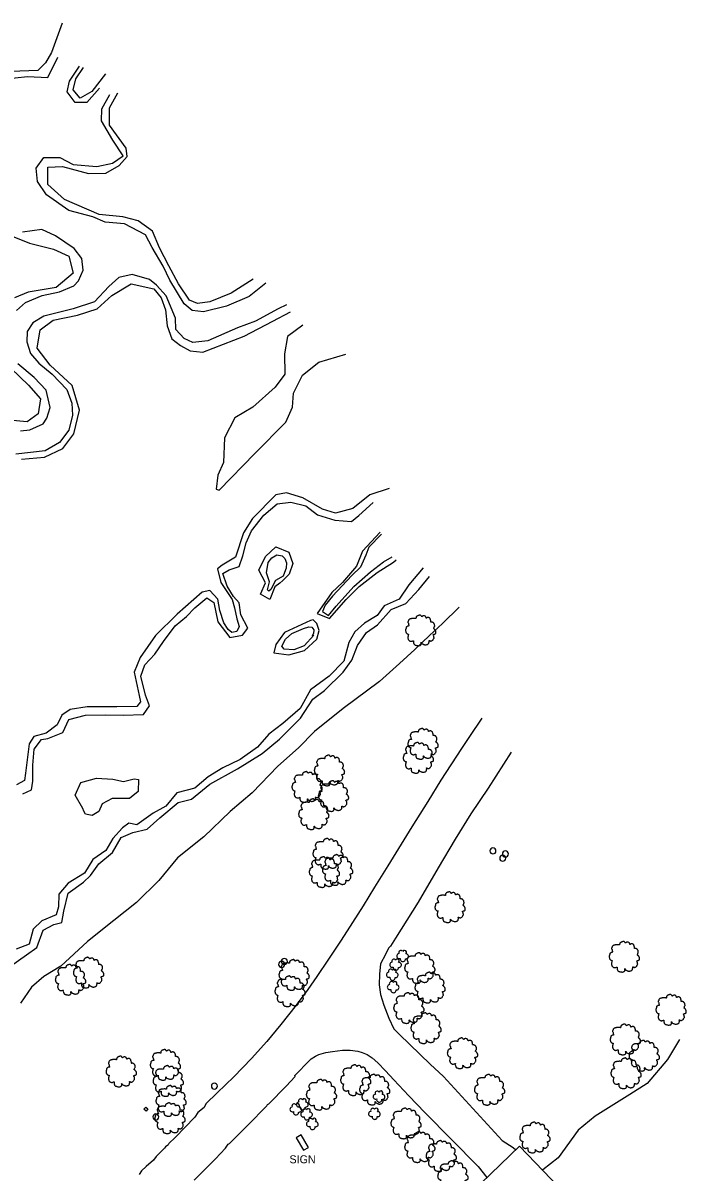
# Model space of a CAD drawing. Extents: x 2160437 to 2172832, y 205694 to 212444.
# Drawn here: x 2172338 to 2172677, y 206825 to 207400 of the extents above; entities that cross this region are included whole.
import ezdxf

# ---------------------------------------------------------------- set-up
doc = ezdxf.new("R2010")
doc.units = 0
for name, color, linetype in [('Default', 7, 'Continuous'), ('RD_EX_Bldg_Signs', 7, 'Continuous'), ('RD_EX_BldgApp_txCode', 7, 'Continuous'), ('RD_EX_Bridge', 7, 'Continuous'), ('RD_EX_H2O', 7, 'Continuous'), ('RD_EX_Misc', 7, 'Continuous'), ('RD_EX_Road', 7, 'Continuous'), ('RD_EX_Road_Post', 7, 'Continuous'), ('RD_EX_VEG', 7, 'Continuous'), ('RD_EX_VEG_ShrubLine', 7, 'Continuous')]:
    doc.layers.add(name, color=color, linetype=linetype)

# ---------------------------------------------------------------- blocks, each defined once
blk = doc.blocks.new('POST')
at = {"layer": 'Default'}
for start, end in [(90, 270), (270, 90)]:
    blk.add_arc((0, 0), 0.0417, start, end, dxfattribs=at)
blk = doc.blocks.new('T2')
at = {"layer": 'RD_EX_VEG'}
for points in [[(0.05, 7.21), (-0.25, 7.24), (-0.57, 7.14), (-0.82, 7.04), (-1.05, 6.96), (-1.27, 6.86), (-1.57, 6.69), (-1.8, 6.49), (-1.92, 6.24), (-1.97, 6.01), (-2.02, 5.74), (-2.02, 5.56), (-2.15, 5.54), (-2.3, 5.56), (-2.55, 5.64), (-2.8, 5.64), (-3.05, 5.64), (-3.4, 5.61), (-3.75, 5.61), (-4.02, 5.56), (-4.35, 5.51), (-4.72, 5.39), (-5.07, 5.26), (-5.37, 5.01), (-5.62, 4.54), (-5.75, 4.19), (-5.9, 3.94), (-5.75, 3.49), (-5.57, 3.14), (-5.55, 2.94), (-5.47, 2.52), (-5.37, 2.29), (-5.25, 2.09), (-5.32, 2.07), (-5.7, 2.02), (-6, 1.92), (-6.42, 1.69), (-6.64, 1.47), (-6.74, 1.14), (-6.77, 0.79), (-6.87, 0.59), (-6.94, 0.32), (-6.97, 0.24), (-7.02, -0.08), (-6.92, -0.53), (-6.89, -0.88), (-6.77, -1.11), (-6.62, -1.28), (-6.44, -1.53), (-6.05, -1.76), (-5.72, -1.86), (-5.52, -1.88), (-5.7, -2.38), (-5.75, -2.73), (-5.87, -3.13), (-5.87, -3.21), (-5.92, -3.68), (-5.77, -4.01), (-5.7, -4.38), (-5.52, -4.61), (-5.25, -4.91), (-4.92, -5.13), (-4.42, -5.26), (-4.02, -5.23), (-3.45, -5.06), (-3.2, -4.98), (-3.22, -5.16), (-3.2, -5.53), (-3.2, -5.96), (-3.05, -6.28), (-2.95, -6.56), (-2.8, -6.81), (-2.47, -7.03), (-2.07, -7.11), (-1.65, -7.26), (-1.2, -7.33), (-0.7, -7.36), (-0.1, -7.21), (0.18, -7.08), (0.28, -6.91), (0.48, -6.53), (0.43, -6.31), (0.45, -5.71), (0.55, -5.88), (0.73, -6.23), (1.23, -6.53), (1.63, -6.71), (2.1, -6.86), (2.4, -6.93), (2.88, -6.86), (3.25, -6.78), (3.63, -6.66), (3.93, -6.38), (4.1, -6.11), (4.15, -5.83), (4.23, -5.46), (4.28, -5.28)], [(4.28, -5.28), (4.2, -5.11), (4.15, -4.86), (4.23, -4.88), (4.4, -4.93), (4.68, -5.06), (4.9, -5.13), (5.23, -5.11), (5.5, -5.01), (5.95, -4.73), (6.22, -4.26), (6.5, -3.86), (6.57, -3.53), (6.52, -3.31), (6.5, -2.81), (6.3, -2.56), (6.25, -2.43), (6.15, -2.03), (6.22, -1.98), (6.5, -1.93), (6.87, -1.81), (7.15, -1.68), (7.37, -1.51), (7.45, -1.28), (7.42, -0.88), (7.47, -0.48), (7.4, -0.33), (7.3, -0.18), (7.22, 0.02), (7.07, 0.17), (6.97, 0.32), (6.87, 0.42), (6.75, 0.57), (6.57, 0.69), (6.42, 0.74), (6.37, 0.89), (6.52, 1.09), (6.57, 1.19), (6.6, 1.42), (6.82, 1.77), (6.87, 2.17), (6.82, 2.59), (6.77, 2.87), (6.62, 3.14), (6.42, 3.39), (6.3, 3.56), (6.12, 3.69), (5.8, 3.81), (5.55, 3.86), (5.2, 3.86), (5, 3.91), (5.03, 3.96), (5.03, 4.11), (5.03, 4.39), (4.95, 4.84), (4.8, 5.34), (4.8, 5.36), (4.7, 5.61), (4.48, 5.81), (4.3, 5.91), (4.1, 6.04), (3.85, 6.06), (3.55, 6.06), (3.28, 6.01), (3.08, 5.91), (2.9, 5.79), (2.83, 5.94), (2.73, 6.24), (2.68, 6.39), (2.53, 6.56), (2.3, 6.76), (1.85, 6.89), (1.23, 6.81), (0.93, 6.61), (0.78, 6.44), (0.73, 6.56), (0.53, 6.76), (0.43, 6.94), (0.25, 7.06), (0.1, 7.16), (0, 7.21)]]:
    blk.add_spline(points, degree=3, dxfattribs=at)

msp = doc.modelspace()

# ---------------------------------------------------------------- linework, layer by layer
at = {"layer": 'RD_EX_Bldg_Signs'}
msp.add_lwpolyline([(2172480.43, 206837.97), (2172476.75, 206844.2), (2172474.25, 206842.72), (2172477.93, 206836.49)], close=True, dxfattribs=at)
at = {"layer": 'RD_EX_Bridge'}
msp.add_lwpolyline([(2172585.98, 206838.48), (2172676.66, 206743.86), (2172657.52, 206725.51), (2172566.84, 206820.13)], close=True, dxfattribs=at)
at = {"layer": 'RD_EX_H2O'}
for points in [[(2172327.71, 207371.9), (2172340.06, 207373.13), (2172350.11, 207372.67), (2172355.18, 207382.82)], [(2172376.08, 207367.32), (2172369.75, 207360.18), (2172363.89, 207360.23), (2172359.79, 207365.47), (2172360.98, 207370.92), (2172365.94, 207378.38)], [(2172459.18, 207269.95), (2172450.83, 207263.25), (2172439.48, 207258.34), (2172428.06, 207255.59), (2172422.33, 207256.29), (2172418.41, 207259.55), (2172411.11, 207271.46), (2172407.83, 207278.47), (2172402.32, 207287.7), (2172399.02, 207293.99), (2172388.48, 207299.56), (2172378.79, 207300.36), (2172372.76, 207303.13), (2172360.64, 207306.17), (2172349.53, 207314.02), (2172345.02, 207320.77), (2172344.43, 207327.44), (2172348.14, 207332.64), (2172356.23, 207332.78), (2172362.79, 207329.15), (2172374.75, 207328.22), (2172382.5, 207329.83), (2172387.79, 207333.59), (2172382.66, 207341.44), (2172376.94, 207351.08), (2172377.24, 207357.03), (2172381.26, 207364.22)], [(2172334.59, 207256.16), (2172338.96, 207260.24), (2172347.29, 207263.67), (2172356.06, 207265.52), (2172363.15, 207268.56), (2172365.5, 207271.02), (2172367.8, 207276.47), (2172367.24, 207282.31), (2172363.28, 207287.18), (2172354.03, 207293.57), (2172347.16, 207296.73), (2172337.5, 207295.38)], [(2172469.42, 207259.11), (2172465.3, 207257.06), (2172453.96, 207250.99), (2172445.01, 207247.64), (2172430.18, 207241.13), (2172422.74, 207240.17), (2172418.26, 207242.21), (2172414.21, 207246.81), (2172414, 207252.41), (2172409.36, 207263.64), (2172404.54, 207268.91), (2172400.98, 207271.76), (2172392.27, 207274.25), (2172385.71, 207272.79), (2172380.74, 207268.17), (2172373.48, 207260.55), (2172362.82, 207257.02), (2172348.19, 207253.49), (2172342.65, 207250.05), (2172339.94, 207245.71), (2172339.73, 207240.63), (2172341.49, 207234.74), (2172345.74, 207229.84), (2172352.36, 207224.36), (2172359.75, 207216.79), (2172362.16, 207209.89), (2172362.56, 207203.92), (2172360.61, 207196.38), (2172355.98, 207190.29), (2172348.89, 207186.14), (2172334.17, 207184.38)], [(2172336.47, 207196.13), (2172341.16, 207196.61), (2172347.82, 207199.59), (2172349.77, 207202.5), (2172351.41, 207207.84), (2172349.29, 207216.48), (2172343.37, 207222.71), (2172335.24, 207229.65)], [(2172337.67, 207014.59), (2172342.08, 207016.61), (2172342.7, 207021), (2172342.66, 207029.07), (2172343.41, 207037), (2172347.07, 207041.8), (2172350.25, 207042.26), (2172357.7, 207045.34), (2172360.61, 207051.75), (2172368.95, 207054), (2172378.96, 207054.11), (2172387.91, 207053.97), (2172398, 207054.25), (2172401.04, 207058.59), (2172399.03, 207063.96), (2172396.6, 207073.54), (2172398.73, 207079.15), (2172403.62, 207084.55), (2172407.97, 207090.85), (2172413.77, 207098.7), (2172419.56, 207103.28), (2172423.67, 207107.66), (2172429.62, 207112.59), (2172433.12, 207110.25), (2172435.2, 207100.61), (2172441.19, 207092.8), (2172447.54, 207093.94), (2172450.13, 207097.54), (2172446.65, 207104.1), (2172445.82, 207110.2), (2172442.98, 207113.29), (2172439.86, 207118.53), (2172437.6, 207124.75), (2172440.86, 207126.56), (2172445.8, 207128.34), (2172447.68, 207133.63), (2172449.34, 207140.08), (2172451.97, 207146.1), (2172458.2, 207153.97), (2172464.81, 207159.65), (2172471.65, 207160.47), (2172479.19, 207158.63), (2172485.01, 207154.18), (2172493.65, 207151.52), (2172501.89, 207150.74), (2172505.71, 207153.77), (2172512.77, 207160.21)], [(2172516.24, 207145.52), (2172507.53, 207136.01), (2172504.49, 207128.39), (2172497.53, 207120.31), (2172492.1, 207115.36), (2172484.88, 207104.86), (2172490.94, 207102.32), (2172499.31, 207111.87), (2172505.85, 207118.33), (2172514.84, 207125.27), (2172522.93, 207130.49), (2172524.22, 207131.59)], [(2172537.81, 207127.54), (2172530.69, 207119.12), (2172525.73, 207111.94), (2172518.26, 207108.55), (2172514.72, 207103.8), (2172508.51, 207099.95), (2172503.66, 207095.58), (2172500.71, 207090.25), (2172498.07, 207080.95), (2172490.83, 207073.43), (2172481.5, 207066.65), (2172476.27, 207057.26), (2172467.65, 207049.74), (2172460.63, 207044.55), (2172455, 207038), (2172446.25, 207031.8), (2172437.72, 207027.73), (2172430.37, 207023.23), (2172423.72, 207017.46), (2172414.69, 207015.1), (2172409.15, 207008.5), (2172402.8, 207005.03), (2172394.72, 206999.16), (2172390.63, 206999.96), (2172387.44, 206997.6), (2172382.71, 206992.33), (2172379.17, 206986.41), (2172372.65, 206981.86), (2172368.49, 206975.05), (2172360.35, 206969.96), (2172355.71, 206964.44), (2172355.51, 206958.17), (2172354.32, 206954.15), (2172347.17, 206951.25), (2172342.84, 206947.08), (2172340.78, 206939.53), (2172334.35, 206937.05)], [(2172665.98, 206891.85), (2172659.95, 206881.87), (2172649.73, 206869.88), (2172641.12, 206864.46), (2172623.77, 206853.59), (2172615.26, 206846.54), (2172605.28, 206832.74), (2172597.59, 206826.81), (2172597.35, 206826.61)]]:
    msp.add_lwpolyline(points, dxfattribs=at)
for points in [[(2172466.07, 207119.89), (2172463.58, 207118.16), (2172461.18, 207111.72), (2172456.46, 207114.4), (2172459.06, 207120.11), (2172455.59, 207126.46), (2172458.92, 207133.32), (2172464.14, 207138.04), (2172470.59, 207135.43), (2172472.7, 207129.81), (2172470.82, 207124.51), (2172467.57, 207121.33)], [(2172481.47, 207101.33), (2172468.44, 207095.28), (2172464.21, 207089.25), (2172463.16, 207085.07), (2172470.7, 207084.18), (2172478.48, 207086.36), (2172484.71, 207091.9), (2172485.89, 207096.35), (2172484.72, 207099.85), (2172482.89, 207101.64)], [(2172367.61, 207007.36), (2172363.91, 207013.92), (2172366.74, 207020.37), (2172374.48, 207022.47), (2172382.65, 207022.04), (2172388.05, 207020.85), (2172393.32, 207022.17), (2172395.58, 207021.78), (2172395.41, 207015.81), (2172391.08, 207012.37), (2172382.4, 207012.4), (2172377.41, 207009.58), (2172375.61, 207005.84), (2172372.27, 207003.87), (2172369.09, 207004.57), (2172368.26, 207006.01)]]:
    msp.add_lwpolyline(points, close=True, dxfattribs=at)
at = {"layer": 'RD_EX_Misc'}
msp.add_lwpolyline([(2172399.37, 206856.08), (2172398.25, 206856.99), (2172399.12, 206858.06), (2172400.24, 206857.15)], close=True, dxfattribs=at)
at = {"layer": 'RD_EX_Road'}
for points in [[(2172567.11, 207052.41), (2172560.98, 207043.37), (2172556.95, 207037.34), (2172556.95, 207037.34), (2172546.62, 207021.48), (2172540.07, 207010.84), (2172532.13, 206998.22), (2172526.77, 206989.51), (2172520.08, 206978.73), (2172513.46, 206968.01), (2172507.77, 206958.74), (2172502.41, 206950.28), (2172496.74, 206941.49), (2172490.46, 206932.01), (2172484.66, 206923.42), (2172480.22, 206916.9), (2172474.3, 206909.05), (2172466.57, 206899.32), (2172459.59, 206890.94), (2172451.97, 206882.45), (2172443.08, 206873.2), (2172434.79, 206865.14), (2172429.18, 206859.65), (2172428.35, 206857.88), (2172425.19, 206855.32), (2172423.63, 206853), (2172413.89, 206842.97), (2172410.64, 206839.95), (2172410.34, 206839.28), (2172410.09, 206839.01), (2172409, 206838.29), (2172408.56, 206837.53), (2172408.15, 206837.29), (2172404.32, 206833.32), (2172403.03, 206831.61), (2172399.33, 206828.41), (2172397.01, 206826.15), (2172395.79, 206824.41)], [(2172581.82, 207035.55), (2172570.25, 207017.56), (2172561.6, 207004.61), (2172553.71, 206991.94), (2172545.23, 206977.68), (2172535.31, 206960.47), (2172523.92, 206942.45), (2172521.51, 206938.59), (2172520.43, 206937.44), (2172518.97, 206934.39), (2172516.39, 206929.62), (2172515.89, 206924.61), (2172515.77, 206919.23), (2172516.42, 206914.34), (2172518.2, 206908.98), (2172520.62, 206902.52), (2172523.14, 206897.27), (2172525.93, 206894.29), (2172541.37, 206879.6), (2172547.95, 206873.33), (2172577.23, 206841.42), (2172582.79, 206837.93), (2172584.14, 206836.71)], [(2172423.36, 206821.58), (2172429.11, 206827.43), (2172433.97, 206832.22), (2172439.05, 206837.55), (2172440.4, 206839.53), (2172441.07, 206839.84), (2172450.14, 206848.99), (2172459.62, 206858.78), (2172459.91, 206859.41), (2172460.59, 206859.68), (2172469.3, 206868.5), (2172473.74, 206873.31), (2172473.68, 206873.84), (2172475.2, 206875.3), (2172479.66, 206880.1), (2172481.81, 206882.16), (2172483.9, 206883.48), (2172485.68, 206884.44), (2172489.11, 206885.33), (2172492.53, 206885.84), (2172497.43, 206886.5), (2172501.37, 206886.48), (2172505.07, 206886.06), (2172507.34, 206885.33), (2172509.88, 206884.3), (2172512.35, 206882.67), (2172515.19, 206880.24), (2172518.96, 206876.26), (2172523.06, 206871.77), (2172530.71, 206863.69), (2172538.63, 206855.46), (2172565.36, 206828.39), (2172569.69, 206822.86)]]:
    msp.add_lwpolyline(points, dxfattribs=at)
at = {"layer": 'RD_EX_VEG'}
for centre, radius, start, end in [((2172523.15, 206930.93), 1.08, 34.97629, 204.75602), ((2172524.92, 206931.08), 0.995, 308.76261, 152.04674), ((2172525.82, 206933.56), 1.26, 96.45179, 294.73401), ((2172526.66, 206935.27), 1.08, 34.97629, 204.75602), ((2172527.63, 206932.12), 1.32, 166.88266, 5.75893), ((2172528.43, 206935.42), 0.995, 308.76261, 152.04674), ((2172529.22, 206933.44), 1.22, 256.56668, 98.10463), ((2172521.5, 206925.91), 1.08, 34.97629, 204.75602), ((2172522.31, 206929.22), 1.26, 96.45179, 294.73401), ((2172523.27, 206926.06), 0.995, 308.76261, 152.04674), ((2172524.12, 206927.78), 1.32, 166.88266, 5.75893), ((2172525.71, 206929.1), 1.22, 256.56668, 98.10463), ((2172520.66, 206924.2), 1.26, 96.45179, 294.73401), ((2172521.96, 206919.74), 1.08, 34.97629, 204.75602), ((2172522.47, 206922.76), 1.32, 166.88266, 5.75893), ((2172523.73, 206919.89), 0.995, 308.76261, 152.04674), ((2172524.06, 206924.08), 1.22, 256.56668, 98.10463), ((2172521.12, 206918.03), 1.26, 96.45179, 294.73401), ((2172522.93, 206916.59), 1.32, 166.88266, 5.75893), ((2172524.52, 206917.91), 1.22, 256.56668, 98.10463), ((2172514.05, 206863.3), 1.26, 96.45179, 294.73401), ((2172514.89, 206865.01), 1.08, 34.97629, 204.75602), ((2172516.66, 206865.16), 0.995, 308.76261, 152.04674), ((2172517.45, 206863.18), 1.22, 256.56668, 98.10463), ((2172472.45, 206856.95), 1.26, 96.45179, 294.73401), ((2172473.29, 206858.66), 1.08, 34.97629, 204.75602), ((2172475.06, 206858.81), 0.995, 308.76261, 152.04674), ((2172475.73, 206859.4), 1.26, 96.45179, 294.73401), ((2172476.57, 206861.11), 1.08, 34.97629, 204.75602), ((2172475.85, 206856.83), 1.22, 256.56668, 98.10463), ((2172477.54, 206857.96), 1.32, 166.88266, 5.75893), ((2172478.34, 206861.26), 0.995, 308.76261, 152.04674), ((2172478.67, 206856.15), 1.08, 34.97629, 204.75602), ((2172479.13, 206859.28), 1.22, 256.56668, 98.10463), ((2172480.44, 206856.3), 0.995, 308.76261, 152.04674), ((2172512.6, 206856.41), 1.08, 34.97629, 204.75602), ((2172514.37, 206856.56), 0.995, 308.76261, 152.04674), ((2172515.86, 206861.86), 1.32, 166.88266, 5.75893), ((2172474.26, 206855.51), 1.32, 166.88266, 5.75893), ((2172477.83, 206854.44), 1.26, 96.45179, 294.73401), ((2172479.64, 206853), 1.32, 166.88266, 5.75893), ((2172481.53, 206851.33), 1.08, 34.97629, 204.75602), ((2172481.23, 206854.32), 1.22, 256.56668, 98.10463), ((2172483.3, 206851.48), 0.995, 308.76261, 152.04674), ((2172511.76, 206854.7), 1.26, 96.45179, 294.73401), ((2172513.57, 206853.26), 1.32, 166.88266, 5.75893), ((2172515.16, 206854.58), 1.22, 256.56668, 98.10463), ((2172480.69, 206849.62), 1.26, 96.45179, 294.73401), ((2172482.5, 206848.18), 1.32, 166.88266, 5.75893), ((2172484.09, 206849.5), 1.22, 256.56668, 98.10463)]:
    msp.add_arc(centre, radius, start, end, dxfattribs=at)
at = {"layer": 'RD_EX_VEG_ShrubLine'}
for points in [[(2172357.39, 207399.94), (2172351.96, 207385.12), (2172348.96, 207379.98), (2172345.26, 207376.12), (2172331.67, 207375.64)], [(2172378.95, 207374.52), (2172372.24, 207365.74), (2172366.43, 207362.42), (2172362.91, 207366.61), (2172364.25, 207372.09), (2172368.02, 207377.73)], [(2172452.84, 207271.88), (2172441.9, 207264.84), (2172431.13, 207260.49), (2172424.99, 207259.68), (2172420.98, 207261.42), (2172415.5, 207269.5), (2172410.7, 207278.55), (2172406.07, 207287.52), (2172402.53, 207295.88), (2172395.37, 207301), (2172387.66, 207303.05), (2172375.8, 207304.23), (2172358.48, 207311.67), (2172350.19, 207319.22), (2172350.25, 207327.96), (2172357.51, 207328.15), (2172370.57, 207324.7), (2172379.12, 207324.94), (2172385.91, 207328.77), (2172389.85, 207333.15), (2172389.41, 207337.31), (2172380.95, 207348.9), (2172380.98, 207357.55), (2172385.17, 207365.03)], [(2172331.56, 207293.75), (2172341.03, 207289.93), (2172353.04, 207286.97), (2172360.62, 207283.48), (2172362.9, 207274.95), (2172354.44, 207267.72), (2172354.44, 207267.72), (2172340.31, 207265.35), (2172333.58, 207262.56)], [(2172337.02, 207181.97), (2172348.46, 207182.91), (2172357.71, 207187.21), (2172363.12, 207194.55), (2172366.03, 207206.47), (2172362.38, 207218.74), (2172351.31, 207228.85), (2172344.87, 207237.38), (2172346.35, 207246.64), (2172352.89, 207251.33), (2172365.1, 207253.94), (2172374.78, 207257.08), (2172382.21, 207263.71), (2172391.85, 207269.54), (2172403.23, 207267.08), (2172406.8, 207262.6), (2172409.05, 207256.59), (2172409.82, 207248.5), (2172412.18, 207242.02), (2172416.49, 207238.68), (2172421.38, 207236.14), (2172427.71, 207235.38), (2172448.4, 207243.36), (2172462.64, 207250.87), (2172471.53, 207255.52)], [(2172477.61, 207248.94), (2172469.96, 207243.3), (2172468.51, 207234.53), (2172468.58, 207224.42), (2172463.9, 207217.86), (2172452.61, 207207.95), (2172443.62, 207202.64), (2172438.55, 207192.65), (2172437.97, 207180.19), (2172435.09, 207173.87), (2172434.31, 207167.02), (2172435.84, 207166.43), (2172453.61, 207184.74), (2172469.14, 207200.47), (2172472.44, 207207.98), (2172472.96, 207214.95), (2172477.47, 207223.92), (2172485.61, 207230.4), (2172499.2, 207234.41)], [(2172327.28, 207231.68), (2172340.47, 207218.98), (2172346.51, 207212.14), (2172345.32, 207204.67), (2172339.8, 207200.58), (2172330.87, 207201.37)], [(2172520.72, 207167.35), (2172511.17, 207164.06), (2172502.56, 207157.26), (2172493.97, 207154.92), (2172487.55, 207156.89), (2172477.67, 207162.65), (2172469.54, 207165.08), (2172464.14, 207164.14), (2172452.52, 207152.36), (2172447.95, 207145.11), (2172443.91, 207132.95), (2172437.32, 207128.96), (2172435.01, 207127.14), (2172436.65, 207120.25), (2172442.27, 207111.86), (2172443.42, 207107.63), (2172444.7, 207102.07), (2172445.75, 207098.3), (2172444.63, 207095.85), (2172442.14, 207095.28), (2172440.32, 207096.85), (2172438.17, 207100.06), (2172436.17, 207106.37), (2172435.1, 207111.95), (2172431.22, 207116.25), (2172427.28, 207115.5), (2172414.86, 207104.51), (2172404.03, 207093.75), (2172396.27, 207082.75), (2172393.35, 207075.39), (2172395.8, 207063.78), (2172396.52, 207060.7), (2172394.62, 207058.38), (2172384.74, 207058.1), (2172369.93, 207058.16), (2172361.31, 207056.78), (2172357.27, 207053.96), (2172354.78, 207049.09), (2172349.44, 207044.96), (2172343.24, 207043.4), (2172340.88, 207039.6), (2172339.11, 207024.94), (2172338.58, 207021.37), (2172334.48, 207019.1)], [(2172516.89, 207144.49), (2172510.7, 207137.87), (2172509.16, 207134.02), (2172506.41, 207127.96), (2172502.07, 207123.78), (2172492.47, 207113.41), (2172488.84, 207108.91), (2172487.44, 207105.84), (2172490.41, 207103.75), (2172494.38, 207108.51), (2172503.14, 207118.21), (2172511.5, 207125.64), (2172517.92, 207130.67), (2172522.23, 207133.16)], [(2172330.44, 206927.72), (2172339.56, 206934.27), (2172344.7, 206937.87), (2172347.92, 206946.58), (2172353.22, 206949.37), (2172357.24, 206950.29), (2172358.15, 206956.03), (2172360.41, 206964.96), (2172368.03, 206970.51), (2172371.57, 206973.88), (2172375.72, 206979.73), (2172382.55, 206985.42), (2172386.89, 206992.88), (2172392.68, 206995.34), (2172399.87, 206996.94), (2172406.18, 207002.66), (2172415.31, 207010.38), (2172421.99, 207012.01), (2172431.13, 207019.51), (2172444.97, 207027.1), (2172457.38, 207034.81), (2172465.97, 207042.04), (2172476.46, 207052.53), (2172482.68, 207062), (2172488.52, 207066.23), (2172497.81, 207075.47), (2172502.21, 207081.42), (2172504.92, 207088.77), (2172509.39, 207095.32), (2172515.04, 207099.12), (2172521.79, 207106.75), (2172529.15, 207109.87), (2172535.67, 207116.76), (2172541, 207123.35)], [(2172555.73, 207107.97), (2172547.49, 207099.87), (2172540.93, 207093.84), (2172533.59, 207086.79), (2172526.04, 207079.73), (2172515.92, 207070.77), (2172497.84, 207057.36), (2172483.5, 207045.87), (2172475.51, 207037.63), (2172465.22, 207028.53), (2172452.24, 207015.14), (2172441.35, 207005.89), (2172428.17, 206993.22), (2172415.07, 206982.59), (2172405.59, 206971.31), (2172394.47, 206960.37), (2172383.18, 206951.4), (2172370.1, 206940.82), (2172356.73, 206928.45), (2172348.24, 206923.3), (2172342.01, 206917.98), (2172336.56, 206909.96)]]:
    msp.add_lwpolyline(points, dxfattribs=at)
for points in [[(2172467.81, 207123.48), (2172463.93, 207121.32), (2172461.69, 207116.83), (2172460.65, 207115.93), (2172460.02, 207116.64), (2172460.95, 207120.56), (2172459.55, 207125.2), (2172460.3, 207130.22), (2172462.2, 207132.67), (2172464.68, 207134.11), (2172467.39, 207133.55), (2172468.73, 207132.3), (2172469.51, 207130.04), (2172469.39, 207127.45), (2172468.43, 207125.34)], [(2172483.1, 207093.93), (2172478.37, 207088.66), (2172473.22, 207086.65), (2172468.37, 207086.95), (2172467.19, 207088.55), (2172469.05, 207091.94), (2172472.18, 207094.86), (2172477.97, 207097.32), (2172480.66, 207098.11), (2172482.09, 207097.99), (2172483.13, 207096.56), (2172482.94, 207094.74), (2172482.24, 207093.68)]]:
    msp.add_lwpolyline(points, close=True, dxfattribs=at)

# ---------------------------------------------------------------- block references
at = {"layer": 'RD_EX_Road_Post', "xscale": 36, "yscale": 36}
for p in [(2172572.65, 206986.14), (2172577.55, 206982.48), (2172578.9, 206984.62), (2172468.43, 206930.89), (2172467.06, 206929.44), (2172433.43, 206868.55), (2172404.16, 206853.14)]:
    msp.add_blockref('POST', p, dxfattribs=at)
at = {"layer": 'RD_EX_VEG', "xscale": 1.0499999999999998, "yscale": 1.0499999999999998}
for p in [(2172536.33, 207096.42), (2172537.47, 207039.72), (2172535.14, 207032.72), (2172490.72, 207026.42), (2172479.54, 207018.15), (2172492.74, 207013.63), (2172482.89, 207004.55), (2172490.01, 206984.77), (2172494.8, 206976.66), (2172488.18, 206975.64), (2172551.01, 206958.08), (2172638.11, 206933.31), (2172370.33, 206925.35), (2172473.06, 206924.21), (2172535.89, 206927.65), (2172361.31, 206921.83), (2172471.03, 206916.02), (2172541, 206917.9), (2172530.41, 206907.67), (2172661.46, 206906.79), (2172538.98, 206897.62), (2172638.6, 206891.96), (2172557.24, 206885.08), (2172648.05, 206883.84), (2172408.73, 206879.27), (2172386.66, 206875.95), (2172638.96, 206875.04), (2172410.15, 206871.2), (2172503.84, 206871.63), (2172513.34, 206866.88), (2172570.78, 206866.83), (2172411.56, 206861.24), (2172486.75, 206864.35), (2172411.01, 206852.58), (2172528.99, 206850.01), (2172535.9, 206838.17), (2172593.42, 206842.97), (2172546.6, 206833.73), (2172552.41, 206823.67)]:
    msp.add_blockref('T2', p, dxfattribs=at)

# ---------------------------------------------------------------- texts
at = {"layer": 'RD_EX_BldgApp_txCode'}
msp.add_text('SIGN', height=4, dxfattribs=at).set_placement((2172470.98, 206830))

doc.saveas('drawing.dxf')
